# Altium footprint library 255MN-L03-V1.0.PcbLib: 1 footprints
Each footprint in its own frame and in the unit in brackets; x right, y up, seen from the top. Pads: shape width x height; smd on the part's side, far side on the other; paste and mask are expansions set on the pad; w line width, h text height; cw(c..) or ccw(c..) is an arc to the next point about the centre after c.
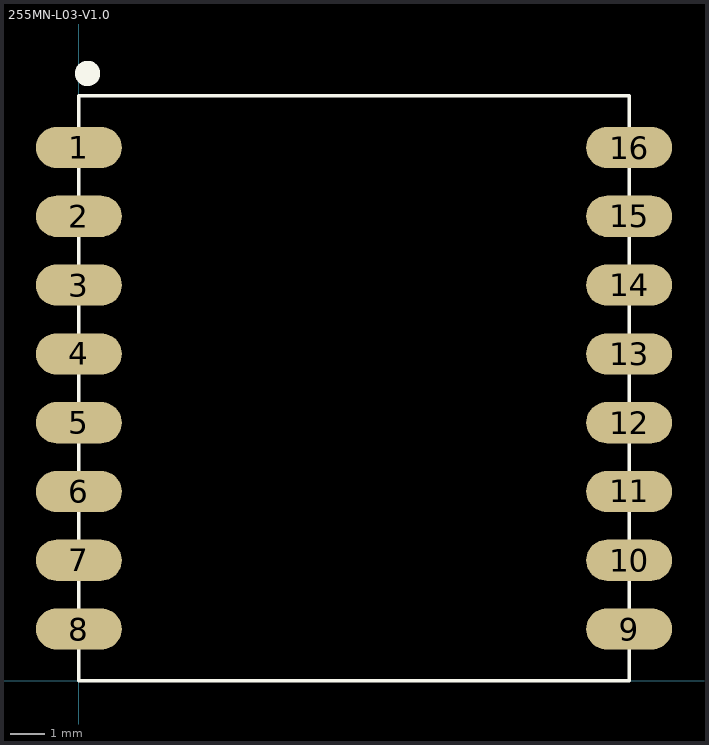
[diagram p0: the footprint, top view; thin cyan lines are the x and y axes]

## 255MN-L03-V1.0 [mm] "255MN-L03-V1.0"
pads (16):
  oval 2.5x1.2 smd: 1(0,15.5) 2(0,13.5) 3(0,11.5) 4(0,9.5) 5(0,7.5) 6(0,5.5) 7(0,3.5) 8(0,1.5) 9(16,1.5) 10(16,3.5) 11(16,5.5) 12(16,7.5) 13(16,9.5) 14(16,11.5) 15(16,13.5) 16(16,15.5)
Top Overlay:
  circle w0.381: c0.254,17.653 r0.178
  lines w0.1: 0,0 0,17 16,17 16,0 0,0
